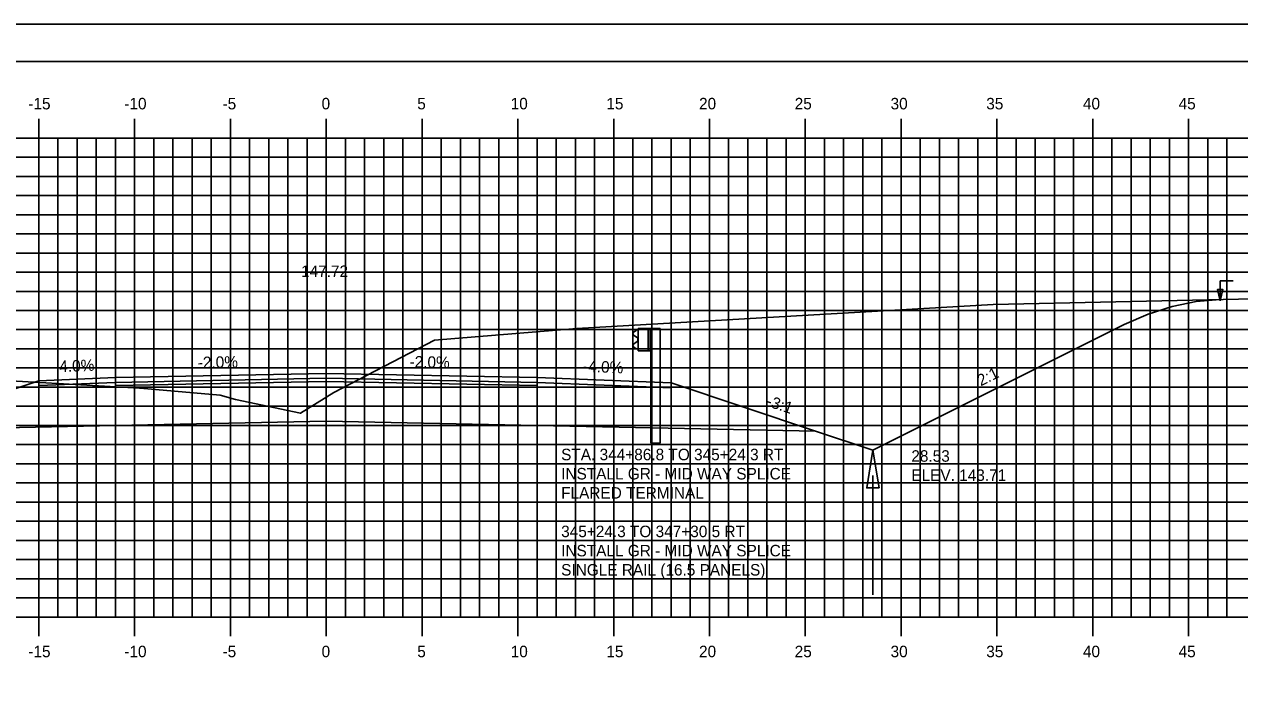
# Model space of a CAD drawing. Extents: x 1143642 to 1143812, y 608981 to 609091.
# Drawn here: x 1143709.1 to 1143772.5, y 609057 to 609091.3 of the extents above; entities that cross this region are included whole.
import ezdxf

# ---------------------------------------------------------------- set-up
doc = ezdxf.new("R2010")
doc.units = 0
for name, color, linetype in [('ANNOTATION', 7, 'Continuous'), ('BORDER', 7, 'Continuous'), ('D_Drainage_Ditch_Line', 7, 'Continuous'), ('D_Guardrail_Beam_Rt', 7, 'Continuous'), ('D_Guardrail_ConcBarrier', 7, 'Continuous'), ('D_Roadway_Centerline', 7, 'Continuous'), ('D_Roadway_Centerline_Text', 7, 'Continuous'), ('D_Roadway_Edge_Shoulder', 7, 'Continuous'), ('D_Roadway_Edge_TW', 7, 'Continuous'), ('D_Roadway_Pavement', 7, 'Continuous'), ('D_Roadway_SlopeLines', 7, 'Continuous'), ('D_Roadway_SubGrade', 7, 'Continuous'), ('D_Text_Standard', 7, 'Continuous'), ('H_V ANNOTATION', 7, 'Continuous'), ('MAJOR', 7, 'Continuous'), ('MINOR', 7, 'Continuous'), ('PLOT BOUNDARY', 7, 'Continuous'), ('S_Roadway_Centerline', 7, 'Continuous')]:
    doc.layers.add(name, color=color, linetype=linetype)

msp = doc.modelspace()

# ---------------------------------------------------------------- linework, layer by layer
msp.add_lwpolyline([(1143689.9, 609072.198), (1143691.15, 609072.231), (1143692.4, 609072.077), (1143693.65, 609071.734), (1143694.9, 609071.203), (1143699.112, 609069.097), (1143702.112, 609070.097), (1143709.835, 609072.671), (1143709.836, 609072.671), (1143713.836, 609072.831), (1143724.836, 609073.051), (1143735.836, 609072.831), (1143742.836, 609072.551), (1143750.368, 609070.041), (1143753.368, 609069.041), (1143766.479, 609075.596), (1143767.729, 609076.147), (1143768.979, 609076.547), (1143770.229, 609076.799), (1143771.479, 609076.901)])
at = {"layer": 'BORDER'}
msp.add_lwpolyline([(1143649.836, 608984.335), (1143809.836, 608984.335), (1143809.836, 609089.335), (1143649.836, 609089.335)], close=True, dxfattribs=at)
at = {"layer": 'D_Drainage_Ditch_Line'}
msp.add_line((1143753.368, 609067.729), (1143753.368, 609061.485), dxfattribs=at)
msp.add_lwpolyline([(1143753.696, 609067.072), (1143753.04, 609067.072), (1143753.368, 609069.041)], close=True, dxfattribs=at)
at = {"layer": 'D_Guardrail_Beam_Rt'}
for p, q in [((1143741.017, 609075.297), (1143740.874, 609075.197)), ((1143740.874, 609075.054), (1143741.069, 609074.918)), ((1143741.107, 609075.318), (1143741.033, 609075.304)), ((1143741.069, 609074.719), (1143740.874, 609074.583)), ((1143740.874, 609074.439), (1143741.017, 609074.339)), ((1143741.103, 609074.853), (1143741.103, 609074.783)), ((1143741.033, 609074.333), (1143741.107, 609074.318))]:
    msp.add_line(p, q, dxfattribs=at)
for centre, major_axis, start_param, end_param in [((1143740.924, 609075.125), (-0.0877, 0), 5.323254, 7.243116), ((1143741.041, 609075.263), (-0.0417, 0), 4.907132, 5.323254), ((1143740.924, 609074.511), (-0.0877, 0), 5.323254, 7.243116), ((1143741.041, 609074.373), (-0.0417, 0), 0.959931, 1.376053), ((1143741.024, 609074.853), (0.0789, 0), 0, 0.959931), ((1143741.024, 609074.783), (0.0789, 0), 5.323254, 6.283185)]:
    msp.add_ellipse(centre, major_axis=major_axis, ratio=0.995501, start_param=start_param, end_param=end_param, dxfattribs=at)
at = {"layer": 'D_Guardrail_ConcBarrier'}
for p, q in [((1143741.107, 609075.402), (1143741.795, 609075.402)), ((1143741.107, 609074.235), (1143741.107, 609075.402)), ((1143741.628, 609075.402), (1143741.628, 609074.235)), ((1143741.732, 609075.402), (1143741.732, 609074.235)), ((1143741.795, 609075.402), (1143742.266, 609075.402)), ((1143741.795, 609075.402), (1143741.795, 609074.235)), ((1143742.266, 609075.402), (1143742.266, 609069.402)), ((1143741.795, 609074.235), (1143741.107, 609074.235)), ((1143741.774, 609069.402), (1143741.774, 609074.235)), ((1143741.774, 609069.402), (1143742.266, 609069.402))]:
    msp.add_line(p, q, dxfattribs=at)
at = {"layer": 'D_Roadway_Edge_Shoulder'}
for points in [[(1143713.836, 609072.831), (1143709.836, 609072.671), (1143709.836, 609072.421), (1143713.836, 609072.581)], [(1143735.836, 609072.831), (1143742.836, 609072.551), (1143742.836, 609072.301), (1143735.836, 609072.581)]]:
    msp.add_lwpolyline(points, close=True, dxfattribs=at)
at = {"layer": 'D_Roadway_Edge_TW'}
msp.add_lwpolyline([(1143713.836, 609072.581), (1143713.836, 609072.831), (1143724.836, 609073.051), (1143735.836, 609072.831), (1143735.836, 609072.581), (1143724.836, 609072.801)], close=True, dxfattribs=at)
at = {"layer": 'D_Roadway_Pavement'}
msp.add_lwpolyline([(1143713.836, 609072.415), (1143713.836, 609072.581), (1143724.836, 609072.801), (1143735.836, 609072.581), (1143735.836, 609072.415), (1143724.836, 609072.635)], close=True, dxfattribs=at)
at = {"layer": 'D_Roadway_SlopeLines'}
for points in [[(1143753.368, 609069.041), (1143766.479, 609075.596), (1143767.729, 609076.147), (1143768.979, 609076.547), (1143770.229, 609076.799), (1143771.479, 609076.901)], [(1143750.368, 609070.041), (1143753.368, 609069.041)]]:
    msp.add_lwpolyline(points, dxfattribs=at)
at = {"layer": 'D_Roadway_SubGrade'}
for points in [[(1143713.836, 609072.415), (1143713.836, 609072.581), (1143709.836, 609072.421), (1143709.836, 609072.671), (1143709.835, 609072.671), (1143702.112, 609070.097), (1143713.836, 609070.331)], [(1143713.836, 609070.331), (1143713.836, 609072.415), (1143724.836, 609072.635), (1143735.836, 609072.415), (1143735.836, 609070.331), (1143724.836, 609070.551)], [(1143735.836, 609072.415), (1143735.836, 609072.581), (1143742.836, 609072.301), (1143742.836, 609072.551), (1143742.836, 609072.551), (1143750.368, 609070.041), (1143735.836, 609070.331)]]:
    msp.add_lwpolyline(points, close=True, dxfattribs=at)
at = {"layer": 'D_Text_Standard'}
msp.add_lwpolyline([(1143771.479, 609076.846), (1143771.489, 609077.877), (1143772.169, 609077.877)], dxfattribs=at)
msp.add_lwpolyline([(1143771.479, 609076.846), (1143771.339, 609077.43), (1143771.63, 609077.427)], close=True, dxfattribs=at)
at = {"layer": 'MAJOR'}
for p, q in [((1143709.836, 609086.337), (1143709.836, 609085.335)), ((1143714.836, 609086.337), (1143714.836, 609085.335)), ((1143719.836, 609086.337), (1143719.836, 609085.335)), ((1143724.836, 609086.337), (1143724.836, 609085.335)), ((1143729.836, 609086.337), (1143729.836, 609085.335)), ((1143734.836, 609086.337), (1143734.836, 609085.335)), ((1143739.836, 609086.337), (1143739.836, 609085.335)), ((1143744.836, 609086.337), (1143744.836, 609085.335)), ((1143749.836, 609086.337), (1143749.836, 609085.335)), ((1143754.836, 609086.337), (1143754.836, 609085.335)), ((1143759.836, 609086.337), (1143759.836, 609085.335)), ((1143764.836, 609086.337), (1143764.836, 609085.335)), ((1143769.836, 609086.337), (1143769.836, 609085.335)), ((1143654.836, 609085.335), (1143794.836, 609085.335)), ((1143654.836, 609085.335), (1143794.836, 609085.335)), ((1143709.836, 609060.335), (1143709.836, 609085.335)), ((1143714.836, 609060.335), (1143714.836, 609085.335)), ((1143719.836, 609060.335), (1143719.836, 609085.335)), ((1143724.836, 609060.335), (1143724.836, 609085.335)), ((1143729.836, 609060.335), (1143729.836, 609085.335)), ((1143734.836, 609060.335), (1143734.836, 609085.335)), ((1143739.836, 609060.335), (1143739.836, 609085.335)), ((1143744.836, 609060.335), (1143744.836, 609085.335)), ((1143749.836, 609060.335), (1143749.836, 609085.335)), ((1143754.836, 609060.335), (1143754.836, 609085.335)), ((1143759.836, 609060.335), (1143759.836, 609085.335)), ((1143764.836, 609060.335), (1143764.836, 609085.335)), ((1143769.836, 609060.335), (1143769.836, 609085.335)), ((1143654.836, 609080.335), (1143794.836, 609080.335)), ((1143654.836, 609075.335), (1143794.836, 609075.335)), ((1143654.836, 609070.335), (1143794.836, 609070.335)), ((1143654.836, 609065.335), (1143794.836, 609065.335)), ((1143654.836, 609060.335), (1143794.836, 609060.335)), ((1143654.836, 609060.335), (1143794.836, 609060.335)), ((1143709.836, 609059.333), (1143709.836, 609060.335)), ((1143714.836, 609059.333), (1143714.836, 609060.335)), ((1143719.836, 609059.333), (1143719.836, 609060.335)), ((1143724.836, 609059.333), (1143724.836, 609060.335)), ((1143729.836, 609059.333), (1143729.836, 609060.335)), ((1143734.836, 609059.333), (1143734.836, 609060.335)), ((1143739.836, 609059.333), (1143739.836, 609060.335)), ((1143744.836, 609059.333), (1143744.836, 609060.335)), ((1143749.836, 609059.333), (1143749.836, 609060.335)), ((1143754.836, 609059.333), (1143754.836, 609060.335)), ((1143759.836, 609059.333), (1143759.836, 609060.335)), ((1143764.836, 609059.333), (1143764.836, 609060.335)), ((1143769.836, 609059.333), (1143769.836, 609060.335))]:
    msp.add_line(p, q, dxfattribs=at)
at = {"layer": 'MINOR'}
for p, q in [((1143710.836, 609060.335), (1143710.836, 609085.335)), ((1143711.836, 609060.335), (1143711.836, 609085.335)), ((1143712.836, 609060.335), (1143712.836, 609085.335)), ((1143713.836, 609060.335), (1143713.836, 609085.335)), ((1143715.836, 609060.335), (1143715.836, 609085.335)), ((1143716.836, 609060.335), (1143716.836, 609085.335)), ((1143717.836, 609060.335), (1143717.836, 609085.335)), ((1143718.836, 609060.335), (1143718.836, 609085.335)), ((1143720.836, 609060.335), (1143720.836, 609085.335)), ((1143721.836, 609060.335), (1143721.836, 609085.335)), ((1143722.836, 609060.335), (1143722.836, 609085.335)), ((1143723.836, 609060.335), (1143723.836, 609085.335)), ((1143725.836, 609060.335), (1143725.836, 609085.335)), ((1143726.836, 609060.335), (1143726.836, 609085.335)), ((1143727.836, 609060.335), (1143727.836, 609085.335)), ((1143728.836, 609060.335), (1143728.836, 609085.335)), ((1143730.836, 609060.335), (1143730.836, 609085.335)), ((1143731.836, 609060.335), (1143731.836, 609085.335)), ((1143732.836, 609060.335), (1143732.836, 609085.335)), ((1143733.836, 609060.335), (1143733.836, 609085.335)), ((1143735.836, 609060.335), (1143735.836, 609085.335)), ((1143736.836, 609060.335), (1143736.836, 609085.335)), ((1143737.836, 609060.335), (1143737.836, 609085.335)), ((1143738.836, 609060.335), (1143738.836, 609085.335)), ((1143740.836, 609060.335), (1143740.836, 609085.335)), ((1143741.836, 609060.335), (1143741.836, 609085.335)), ((1143742.836, 609060.335), (1143742.836, 609085.335)), ((1143743.836, 609060.335), (1143743.836, 609085.335)), ((1143745.836, 609060.335), (1143745.836, 609085.335)), ((1143746.836, 609060.335), (1143746.836, 609085.335)), ((1143747.836, 609060.335), (1143747.836, 609085.335)), ((1143748.836, 609060.335), (1143748.836, 609085.335)), ((1143750.836, 609060.335), (1143750.836, 609085.335)), ((1143751.836, 609060.335), (1143751.836, 609085.335)), ((1143752.836, 609060.335), (1143752.836, 609085.335)), ((1143753.836, 609060.335), (1143753.836, 609085.335)), ((1143755.836, 609060.335), (1143755.836, 609085.335)), ((1143756.836, 609060.335), (1143756.836, 609085.335)), ((1143757.836, 609060.335), (1143757.836, 609085.335)), ((1143758.836, 609060.335), (1143758.836, 609085.335)), ((1143760.836, 609060.335), (1143760.836, 609085.335)), ((1143761.836, 609060.335), (1143761.836, 609085.335)), ((1143762.836, 609060.335), (1143762.836, 609085.335)), ((1143763.836, 609060.335), (1143763.836, 609085.335)), ((1143765.836, 609060.335), (1143765.836, 609085.335)), ((1143766.836, 609060.335), (1143766.836, 609085.335)), ((1143767.836, 609060.335), (1143767.836, 609085.335)), ((1143768.836, 609060.335), (1143768.836, 609085.335)), ((1143770.836, 609060.335), (1143770.836, 609085.335)), ((1143771.836, 609060.335), (1143771.836, 609085.335)), ((1143654.836, 609084.335), (1143794.836, 609084.335)), ((1143654.836, 609083.335), (1143794.836, 609083.335)), ((1143654.836, 609082.335), (1143794.836, 609082.335)), ((1143654.836, 609081.335), (1143794.836, 609081.335)), ((1143654.836, 609079.335), (1143794.836, 609079.335)), ((1143654.836, 609078.335), (1143794.836, 609078.335)), ((1143654.836, 609077.335), (1143794.836, 609077.335)), ((1143654.836, 609076.335), (1143794.836, 609076.335)), ((1143654.836, 609074.335), (1143794.836, 609074.335)), ((1143654.836, 609073.335), (1143794.836, 609073.335)), ((1143654.836, 609072.335), (1143794.836, 609072.335)), ((1143654.836, 609071.335), (1143794.836, 609071.335)), ((1143654.836, 609069.335), (1143794.836, 609069.335)), ((1143654.836, 609068.335), (1143794.836, 609068.335)), ((1143654.836, 609067.335), (1143794.836, 609067.335)), ((1143654.836, 609066.335), (1143794.836, 609066.335)), ((1143654.836, 609064.335), (1143794.836, 609064.335)), ((1143654.836, 609063.335), (1143794.836, 609063.335)), ((1143654.836, 609062.335), (1143794.836, 609062.335)), ((1143654.836, 609061.335), (1143794.836, 609061.335))]:
    msp.add_line(p, q, dxfattribs=at)
at = {"layer": 'PLOT BOUNDARY'}
msp.add_lwpolyline([(1143641.743, 608981.276), (1143811.743, 608981.276), (1143811.743, 609091.276), (1143641.743, 609091.276)], close=True, dxfattribs=at)
at = {"layer": 'S_Roadway_Centerline'}
msp.add_lwpolyline([(1143654.836, 609073.452), (1143656.779, 609073.558), (1143670.077, 609074.012), (1143673.562, 609073.936), (1143684.029, 609071.706), (1143685.439, 609071.188), (1143689.293, 609072.087), (1143689.817, 609072.189), (1143692.998, 609072.514), (1143693.234, 609072.55), (1143703.514, 609072.846), (1143704.706, 609072.868), (1143705.911, 609072.799), (1143715.089, 609072.281), (1143715.529, 609072.252), (1143719.31, 609071.914), (1143720.106, 609071.688), (1143723.487, 609070.975), (1143725.236, 609072.046), (1143730.481, 609074.786), (1143737.909, 609075.389), (1143759.635, 609076.642), (1143794.836, 609077.413)], dxfattribs=at)

# ---------------------------------------------------------------- texts
at = {"layer": 'ANNOTATION'}
for s, rotation, p in [('-4.0%', 2.29061, (1143710.652, 609073.105)), ('-2.0%', 1.14576, (1143718.139, 609073.318)), ('-2.0%', 358.85424, (1143729.179, 609073.365)), ('-4.0%', 357.70939, (1143738.232, 609073.136)), ('2:1', 26.56505, (1143758.996, 609072.373)), ('-3:1', 341.56522, (1143747.752, 609071.367))]:
    msp.add_text(s, height=0.6, rotation=rotation, dxfattribs=at).set_placement(p)
for s, p in [('STA. 344+86.8 TO 345+24.3 RT', (1143737.096, 609068.518)), ('INSTALL GR - MID WAY SPLICE', (1143737.096, 609067.516)), ('FLARED TERMINAL', (1143737.096, 609066.514)), ('345+24.3 TO 347+30.5 RT', (1143737.096, 609064.503)), ('INSTALL GR - MID WAY SPLICE', (1143737.096, 609063.501)), ('SINGLE RAIL (16.5 PANELS)', (1143737.096, 609062.499))]:
    msp.add_text(s, height=0.6, dxfattribs=at).set_placement(p)
at = {"layer": 'D_Roadway_Centerline'}
for s, p in [('C', (1143724.831, 609073.051)), ('L', (1143724.836, 609073.044))]:
    msp.add_text(s, height=0.0146, dxfattribs=at).set_placement(p)
at = {"layer": 'D_Roadway_Centerline_Text'}
msp.add_text('147.72', height=0.6, dxfattribs=at).set_placement((1143723.522, 609078.083))
at = {"layer": 'D_Text_Standard'}
for s, p in [('28.53', (1143755.368, 609068.441)), ('ELEV. 143.71', (1143755.368, 609067.439))]:
    msp.add_text(s, height=0.6, dxfattribs=at).set_placement(p)
at = {"layer": 'H_V ANNOTATION'}
for s, p in [('-15', (1143709.293, 609086.835)), ('-10', (1143714.301, 609086.835)), ('-5', (1143719.427, 609086.835)), ('0', (1143724.595, 609086.835)), ('5', (1143729.587, 609086.835)), ('10', (1143734.462, 609086.835)), ('15', (1143739.453, 609086.835)), ('20', (1143744.29, 609086.835)), ('25', (1143749.282, 609086.835)), ('30', (1143754.285, 609086.835)), ('35', (1143759.277, 609086.835)), ('40', (1143764.322, 609086.835)), ('45', (1143769.314, 609086.835)), ('-15', (1143709.293, 609058.235)), ('-10', (1143714.301, 609058.235)), ('-5', (1143719.427, 609058.235)), ('0', (1143724.595, 609058.235)), ('5', (1143729.587, 609058.235)), ('10', (1143734.462, 609058.235)), ('15', (1143739.453, 609058.235)), ('20', (1143744.29, 609058.235)), ('25', (1143749.282, 609058.235)), ('30', (1143754.285, 609058.235)), ('35', (1143759.277, 609058.235)), ('40', (1143764.322, 609058.235)), ('45', (1143769.314, 609058.235))]:
    msp.add_text(s, height=0.6, dxfattribs=at).set_placement(p)

doc.saveas('drawing.dxf')
